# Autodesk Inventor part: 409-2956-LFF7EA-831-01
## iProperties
Created: 2010-09
Part Number: 409-2956-LFF7EA-831-01
Material: 3/8" OD TUBE - SS
Document SubType Name: Modeling
Designer: S. Boerckel
Engineer: Steve Boerckel
Mass: 61.6007 g
Surface Area: 127.01 cm^2
Volume: 7.62385 cm^3
Density: 8.08 g/cm^3
Description: LOWE PRESSURE GAUGE TUBE
Length: 13.797 in
Author: S. Boerckel
Revision Number: 0
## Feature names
1. Sweep3
